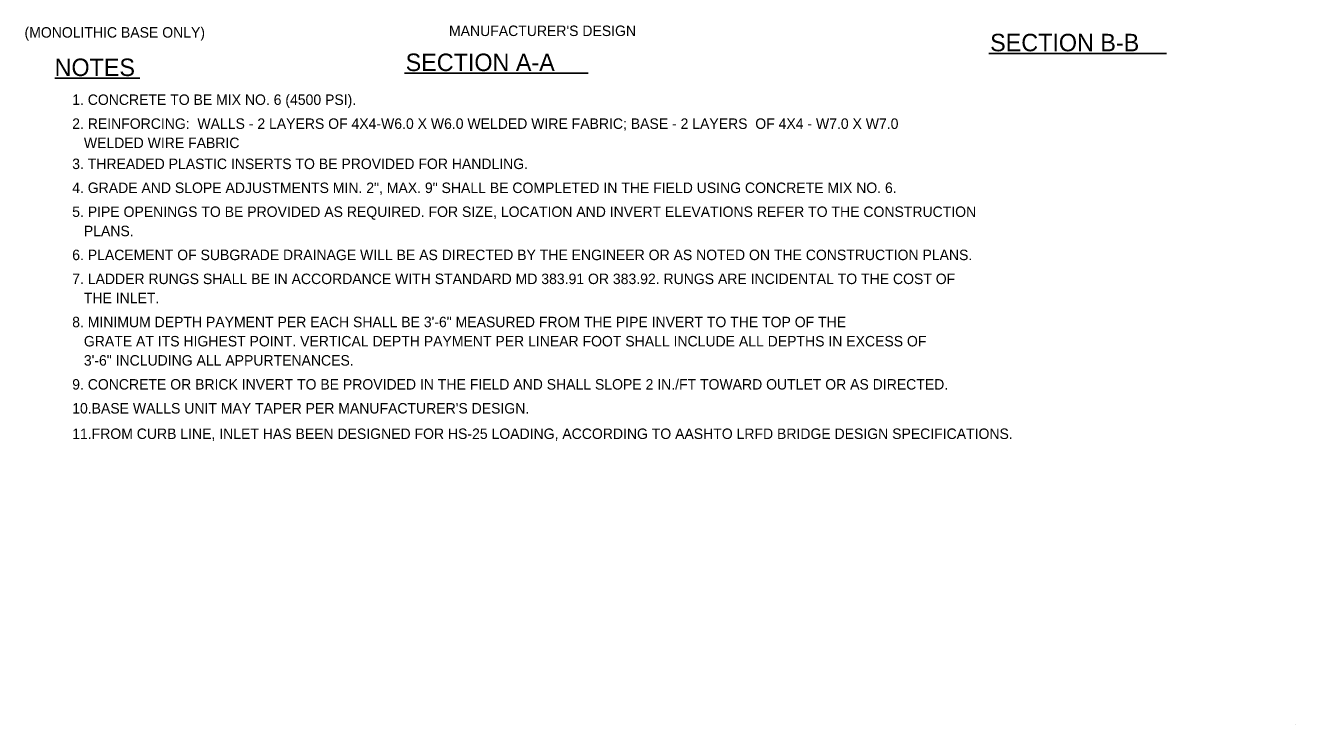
# Model space of a CAD drawing. Extents: x 9.6 to 16.8, y 2.2 to 12.2.
# Drawn here: x 9.56 to 16.84, y 2.15 to 6.16 of the extents above; entities that cross this region are included whole.
import ezdxf

# ---------------------------------------------------------------- set-up
doc = ezdxf.new("R2010")
doc.units = 0
for name, color, linetype in [('DETL-NOTE', 7, 'Continuous'), ('DETL-TITL', 7, 'Continuous'), ('TTLB-TEXT', 7, 'Continuous')]:
    doc.layers.add(name, color=color, linetype=linetype)

msp = doc.modelspace()

# ---------------------------------------------------------------- linework, layer by layer
at = {"layer": 'DETL-NOTE'}
msp.add_line((9.73, 5.8574), (10.2175, 5.8574), dxfattribs=at)
at = {"layer": 'DETL-TITL'}
for p, q in [((15.0822, 5.9992), (16.101, 5.9992)), ((11.7338, 5.8859), (12.786, 5.8859))]:
    msp.add_line(p, q, dxfattribs=at)
at = {"layer": 'TTLB-TEXT'}
msp.add_line((16.8405, 2.1534), (16.8405, 2.1534), dxfattribs=at)

# ---------------------------------------------------------------- texts
at = {"layer": 'DETL-NOTE'}
for s, height, p in [('(MONOLITHIC BASE ONLY)', 0.06, (9.5564, 6.0901)), ("MANUFACTURER'S DESIGN", 0.06, (11.989, 6.0992)), ('NOTES', 0.1, (9.7287, 5.87)), ('1. CONCRETE TO BE MIX NO. 6 (4500 PSI).', 0.06, (9.8296, 5.7044)), ('2. REINFORCING:  WALLS - 2 LAYERS OF 4X4-W6.0 X W6.0 WELDED WIRE FABRIC; BASE - 2 LAYERS  OF 4X4 - W7.0 X W7.0 ', 0.06, (9.8296, 5.5671)), ('   WELDED WIRE FABRIC', 0.06, (9.8296, 5.4571)), ('3. THREADED PLASTIC INSERTS TO BE PROVIDED FOR HANDLING.', 0.06, (9.8296, 5.3368)), ('4. GRADE AND SLOPE ADJUSTMENTS MIN. 2", MAX. 9" SHALL BE COMPLETED IN THE FIELD USING CONCRETE MIX NO. 6.', 0.06, (9.8296, 5.1995)), ('5. PIPE OPENINGS TO BE PROVIDED AS REQUIRED. FOR SIZE, LOCATION AND INVERT ELEVATIONS REFER TO THE CONSTRUCTION', 0.06, (9.8296, 5.0623)), ('   PLANS.', 0.06, (9.8296, 4.9523)), ('6. PLACEMENT OF SUBGRADE DRAINAGE WILL BE AS DIRECTED BY THE ENGINEER OR AS NOTED ON THE CONSTRUCTION PLANS.', 0.06, (9.8296, 4.815)), ('7. LADDER RUNGS SHALL BE IN ACCORDANCE WITH STANDARD MD 383.91 OR 383.92. RUNGS ARE INCIDENTAL TO THE COST OF', 0.06, (9.8296, 4.6777)), ('   THE INLET.', 0.06, (9.8296, 4.5677)), ('8. MINIMUM DEPTH PAYMENT PER EACH SHALL BE 3\'-6" MEASURED FROM THE PIPE INVERT TO THE TOP OF THE', 0.06, (9.8296, 4.4305)), ('   GRATE AT ITS HIGHEST POINT. VERTICAL DEPTH PAYMENT PER LINEAR FOOT SHALL INCLUDE ALL DEPTHS IN EXCESS OF', 0.06, (9.8296, 4.3205)), ('   3\'-6" INCLUDING ALL APPURTENANCES.', 0.06, (9.8296, 4.2105)), ('9. CONCRETE OR BRICK INVERT TO BE PROVIDED IN THE FIELD AND SHALL SLOPE 2 IN./FT TOWARD OUTLET OR AS DIRECTED.', 0.06, (9.8296, 4.0732)), ("10.BASE WALLS UNIT MAY TAPER PER MANUFACTURER'S DESIGN.", 0.06, (9.8296, 3.936)), ('11.FROM CURB LINE, INLET HAS BEEN DESIGNED FOR HS-25 LOADING, ACCORDING TO AASHTO LRFD BRIDGE DESIGN SPECIFICATIONS.', 0.06, (9.8296, 3.7901))]:
    msp.add_text(s, height=height, dxfattribs=at).set_placement(p)
at = {"layer": 'DETL-TITL'}
for s, p in [('SECTION B-B', (15.0901, 6.0118)), ('SECTION A-A', (11.7406, 5.8985))]:
    msp.add_text(s, height=0.1, dxfattribs=at).set_placement(p)

doc.saveas('drawing.dxf')
